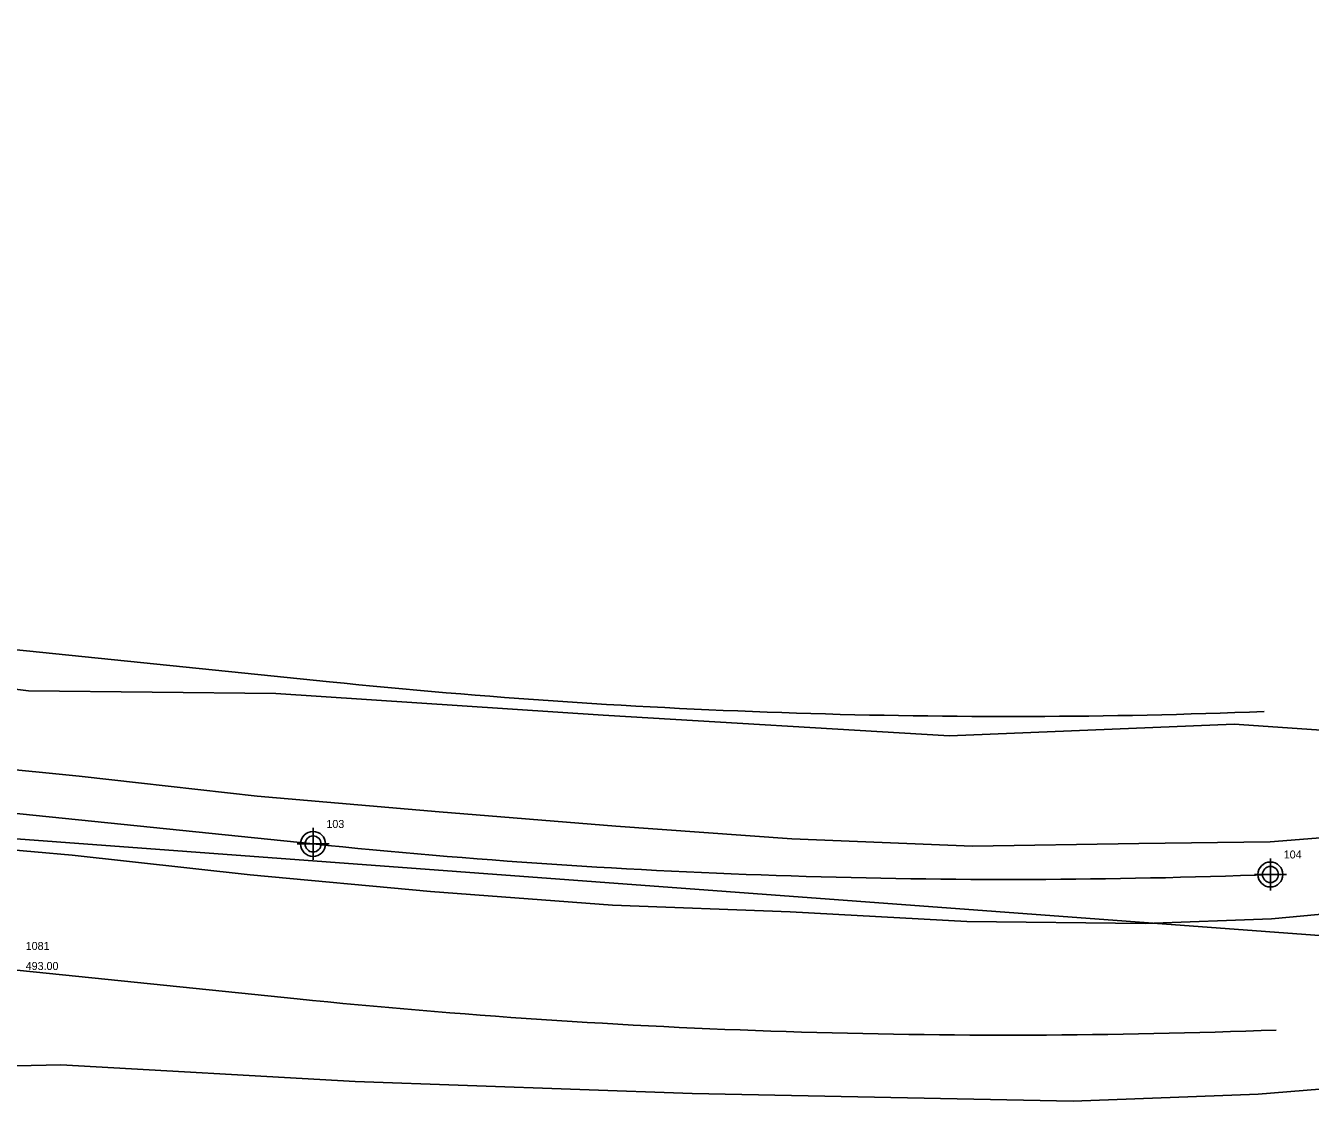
# Model space of a CAD drawing. Extents: x 2060057 to 2062431, y 911685 to 913703.
# Drawn here: x 2061552.2 to 2061792.9, y 912618 to 912819.5 of the extents above; entities that cross this region are included whole.
import ezdxf

# ---------------------------------------------------------------- set-up
doc = ezdxf.new("R2010")
doc.units = 0
for name, color, linetype in [('Cogo Default Point CELL', 7, 'Continuous'), ('COGO Default Point Number', 7, 'Continuous'), ('Exist Horizontal Alignment', 7, 'Continuous'), ('Exist Horizontal Baseline Alignment', 7, 'Continuous'), ('Exist Right of Way Line', 7, 'Continuous'), ('Exist Roads Soil', 7, 'Continuous'), ('Exist Utilities Power Pole Cogo Elevation', 7, 'Continuous'), ('Exist Utilities Power Pole Cogo Number', 7, 'Continuous'), ('Exist Vegetation Woods Line', 7, 'Continuous')]:
    doc.layers.add(name, color=color, linetype=linetype)

msp = doc.modelspace()

# ---------------------------------------------------------------- linework, layer by layer
at = {"layer": 'Cogo Default Point CELL'}
for points in [[(2061606.07, 912669.22), (2061606.07, 912666.22)], [(2061603.07, 912666.22), (2061606.07, 912666.22)], [(2061606.07, 912666.22), (2061609.07, 912666.22)], [(2061606.07, 912666.22), (2061606.07, 912663.22)], [(2061785.44, 912663.5), (2061785.44, 912660.5)], [(2061782.44, 912660.5), (2061785.44, 912660.5)], [(2061785.44, 912660.5), (2061788.44, 912660.5)], [(2061785.44, 912660.5), (2061785.44, 912657.5)]]:
    msp.add_lwpolyline(points, dxfattribs=at)
for centre in [(2061606.07, 912666.22), (2061785.44, 912660.5)]:
    msp.add_circle(centre, 2.34, dxfattribs=at)
at = {"layer": 'Exist Horizontal Alignment'}
for points in [[(2061408.16, 912686.46), (2061606.07, 912666.22)], [(2061785.44, 912660.5), (2061785.44, 912660.5)]]:
    msp.add_lwpolyline(points, dxfattribs=at)
for centre in [(2061606.07, 912666.22), (2061785.44, 912660.5)]:
    msp.add_circle(centre, 1.5, dxfattribs=at)
msp.add_arc((2061736.45, 913940.81), 1281.24, 264.1591, 272.19111, dxfattribs=at)
at = {"layer": 'Exist Horizontal Baseline Alignment'}
msp.add_lwpolyline([(2060519.43, 912752.09), (2061230.37, 912690.89), (2061909.97, 912640.52)], dxfattribs=at)
at = {"layer": 'Exist Right of Way Line'}
for points in [[(2061411.27, 912716.85), (2061609.17, 912696.6)], [(2061405.19, 912657.45), (2061603.1, 912637.2)]]:
    msp.add_lwpolyline(points, dxfattribs=at)
for radius in [1250.7, 1310.41]:
    msp.add_arc((2061736.45, 913940.81), radius, 264.1591, 272.19111, dxfattribs=at)
at = {"layer": 'Exist Roads Soil'}
for p, q in [((2061527.89, 912666.97), (2061560.93, 912664.14)), ((2061560.93, 912664.14), (2061594.28, 912660.42)), ((2061594.28, 912660.42), (2061628.08, 912657.33)), ((2061628.08, 912657.33), (2061662.18, 912654.77)), ((2061662.18, 912654.77), (2061695.47, 912653.5)), ((2061695.47, 912653.5), (2061728.56, 912651.7)), ((2061728.56, 912651.7), (2061761.95, 912651.3)), ((2061761.95, 912651.3), (2061785.66, 912652.17))]:
    msp.add_line(p, q, dxfattribs=at)
for points in [[(2061785.39, 912666.61), (2061760.79, 912666.33), (2061729.65, 912665.79), (2061695.77, 912667.16), (2061662.77, 912669.53), (2061629.67, 912672.23), (2061595.6, 912675.15), (2061562.27, 912678.91), (2061528.97, 912682.23), (2061494.66, 912685.54), (2061457.3, 912688.8)], [(2061785.39, 912666.61), (2061815.15, 912669.02), (2061831.22, 912671.11), (2061851.07, 912674.5)], [(2061785.66, 912652.17), (2061816.54, 912655.08), (2061833.3, 912657.27), (2061853.43, 912660.7)]]:
    msp.add_lwpolyline(points, dxfattribs=at)
at = {"layer": 'Exist Vegetation Woods Line'}
for points in [[(2061885.3, 913033.78), (2061898.7, 913014.07), (2061905.38, 912988.35), (2061912.71, 912961.54), (2061917.62, 912941.08), (2061916.95, 912903.68), (2061921.23, 912855.98), (2061923.79, 912826.53), (2061916.89, 912819.41), (2061910.97, 912803.96), (2061911.85, 912786.51), (2061913.19, 912768.43), (2061924.23, 912758.39), (2061938.19, 912746.33), (2061945, 912738.32), (2061951.68, 912729), (2061952.88, 912722.93), (2061940.73, 912717.7), (2061913.56, 912710.43), (2061848.79, 912691.76), (2061809.49, 912686.57), (2061778.62, 912688.7)], [(2061778.62, 912688.7), (2061725.32, 912686.49), (2061660.42, 912690.37), (2061599.1, 912694.44), (2061552.76, 912694.9), (2061504.88, 912700.89), (2061461.45, 912703.12), (2061425.88, 912707.99), (2061421.01, 912713.38), (2061414.09, 912729.67)], [(2061503.33, 912623.58), (2061558.83, 912624.85), (2061613.97, 912621.69), (2061677.07, 912619.46), (2061748.5, 912618), (2061783.15, 912619.31), (2061794.61, 912620.28)]]:
    msp.add_lwpolyline(points, dxfattribs=at)

# ---------------------------------------------------------------- texts
at = {"layer": 'COGO Default Point Number'}
for s, p in [('103', (2061608.57, 912669.22)), ('104', (2061787.94, 912663.5))]:
    msp.add_text(s, height=1.5, dxfattribs=at).set_placement(p)
at = {"layer": 'Exist Utilities Power Pole Cogo Elevation'}
msp.add_text('493.00', height=1.5, dxfattribs=at).set_placement((2061552.23, 912642.61))
at = {"layer": 'Exist Utilities Power Pole Cogo Number'}
msp.add_text('1081', height=1.5, dxfattribs=at).set_placement((2061552.23, 912646.36))

doc.saveas('drawing.dxf')
